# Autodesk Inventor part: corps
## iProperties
Shininess: 50.0
Length Units: 11269
Angle Units: 11279
Time Units: 11290
Mass Units: 11283
Length Display Precision: 3
Angle Display Precision: 2
Compacted: True
Created: 2001-12
Part Number: corps
Material: Par défaut
Document SubType Name: Modélisation
Designer: pichon
Density: 0.0
Volumn: 0.0
Area: 0.0
PropertySet Name: Model Information
Control State: 0
Master: False
Checked Out: False
Author: pichon
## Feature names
1. Révolution1 [Revolution]
2. Extrusion4
3. Extrusion6
4. Extrusion5
5. Extrusion7
6. Extrusion8
7. Congé12 [Fillet]
8. Congé14 [Fillet]
9. Congé15 [Fillet]
10. Congé16 [Fillet]
11. Congé17 [Fillet]
12. Extrusion1
13. Lissage2
14. Congé18 [Fillet]
15. Congé19 [Fillet]
16. Congé20 [Fillet]
17. Congé21 [Fillet]
18. Congé22 [Fillet]
19. Extrusion11
20. Extrusion12
21. Extrusion13
22. Extrusion14
23. Extrusion15
24. Extrusion16
25. Extrusion17
26. Extrusion18
27. Extrusion19
28. Extrusion20
29. Extrusion21
30. Extrusion22
31. Extrusion23
32. Extrusion24
33. Extrusion25
34. Extrusion26
35. Extrusion27
36. Chanfrein1 [Chamfer]
